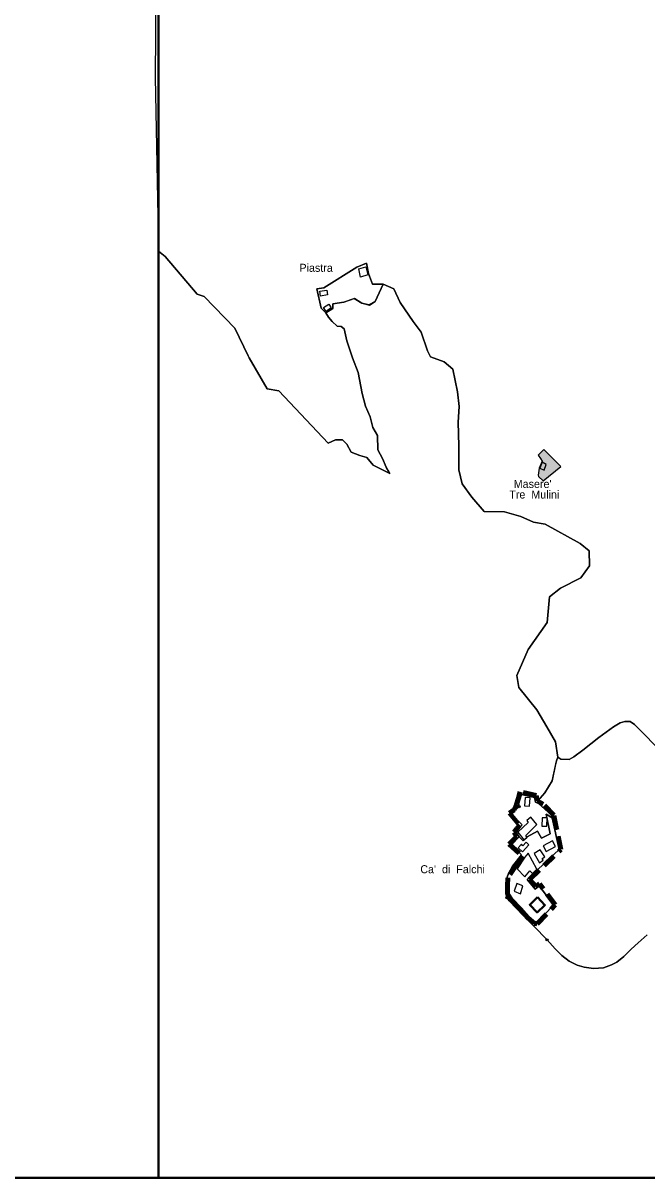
# Model space of a CAD drawing. Extents: x 650071 to 653841, y 889105 to 891996.
# Drawn here: x 652006 to 652784, y 889106 to 890549 of the extents above; entities that cross this region are included whole.
import ezdxf
from ezdxf.enums import TextEntityAlignment as Align

# ---------------------------------------------------------------- set-up
doc = ezdxf.new("R2010")
doc.units = 0
doc.header["$LTSCALE"] = 5.6
doc.header["$PDMODE"] = 32
doc.header["$PDSIZE"] = 2.8
doc.linetypes.add('MEDIUM_DASHED', pattern=[4.5, 3, -1.5])
for name, color, linetype, lineweight in [('2', 7, 'Continuous', 25), ('35', 7, 'Continuous', 25), ('36', 7, 'Continuous', 25), ('4', 7, 'Continuous', 25), ('61', 7, 'Continuous', 35), ('7', 7, 'MEDIUM_DASHED', 100), ('9', 7, 'Continuous', 25)]:
    doc.layers.add(name, color=color, linetype=linetype, lineweight=lineweight)
doc.layers.add('60', color=7, linetype='Continuous')

msp = doc.modelspace()

# ---------------------------------------------------------------- hatches: boundary and pattern name
at = {"layer": '4'}
msp.add_hatch(color=256, dxfattribs=at).paths.add_polyline_path([(652655.57, 890015.75), (652648.32, 890008.92), (652651.05, 890004.87), (652653.25, 890001.32), (652649.63, 889992.42), (652648.51, 889983.98), (652648.82, 889982.17), (652654.45, 889976.86), (652676.76, 889994.67), (652665.71, 890005.72)])

# ---------------------------------------------------------------- linework, layer by layer
at = {"layer": '2'}
msp.add_line((652624.6, 889569.84), (652624.59, 889569.83), dxfattribs=at)
for points in [[(652377.6, 890192.29), (652383.35, 890186.8), (652391.89, 890192.09), (652391.89, 890197.96), (652405.78, 890200.12), (652418.69, 890204.43), (652428.28, 890198.94), (652437.78, 890196.44), (652444.72, 890200.9), (652454.95, 890222.42), (652441.45, 890222.42), (652436.5, 890235.92), (652434.15, 890248.87), (652421.85, 890243.82), (652380.85, 890217.82), (652371.93, 890216.56)], [(652424.52, 890241.64), (652433.17, 890244.24), (652435.94, 890233.94), (652426.63, 890231.2)], [(652375.68, 890213.53), (652384.49, 890215.18), (652385.54, 890209.28), (652376.64, 890207.36)], [(652380.52, 890193.31), (652387.11, 890197.45), (652390, 890192.84), (652383.66, 890188.23)], [(652639.32, 889556.57), (652634.25, 889552.43), (652635.75, 889549.99), (652622.96, 889537.94), (652630.67, 889527.97), (652634.43, 889531.16), (652632.93, 889533.8), (652646.66, 889547.54)], [(652643.42, 889511.43), (652649.91, 889499.78), (652654.64, 889502.76), (652653.38, 889505.22), (652656.58, 889507.1), (652650.75, 889515.95)]]:
    msp.add_lwpolyline(points, close=True, dxfattribs=at)
for points in [[(652665.88, 889555.63), (652664.76, 889559.4), (652648.96, 889573.89), (652644.82, 889575.58), (652643.69, 889581.42), (652627.52, 889584.99), (652623.94, 889574.27), (652624.6, 889569.84)], [(652624.59, 889569.83), (652615, 889560.97), (652628.27, 889547.16), (652620.18, 889537.94), (652624.63, 889532.17), (652629.65, 889527.22), (652634.45, 889531.92)], [(652634.45, 889531.92), (652647.45, 889539.26), (652652.53, 889530.41), (652663.25, 889535.87), (652658.17, 889560.53), (652665.88, 889555.63)]]:
    msp.add_lwpolyline(points, dxfattribs=at)
msp.add_point((652624.6, 889569.84), dxfattribs=at)
at = {"layer": '35'}
msp.add_line((652647.63, 889424.95), (652642.73, 889420.34), dxfattribs=at)
for points in [[(652797.51, 889642.88), (652777.09, 889664.15), (652768.53, 889672.56), (652762.98, 889676.17), (652756.38, 889676.17), (652750.52, 889674.66), (652742.42, 889669.71), (652724.26, 889656.34), (652703.99, 889640.27)], [(652703.99, 889640.27), (652693.04, 889632.01), (652687.03, 889628.56), (652676.83, 889629.01), (652673.09, 889631.71), (652671.14, 889626.92), (652670.16, 889622.28)], [(652670.16, 889622.28), (652665.87, 889601.88), (652656.5, 889586.93), (652647.94, 889576.92), (652648.96, 889573.9), (652664.76, 889559.41), (652665.88, 889555.64), (652674.49, 889516.45), (652634.63, 889478.61), (652644.66, 889466.88), (652649.55, 889470.81), (652667.61, 889447.32), (652647.63, 889424.95), (652642.73, 889420.34), (652659.37, 889403.45)], [(652659.37, 889403.45), (652669.67, 889392.14), (652677.73, 889384), (652686.83, 889376.68), (652697.14, 889371.62), (652705.85, 889369.1), (652717.27, 889367.75), (652729.84, 889368.52), (652739.9, 889372.01), (652746.48, 889375.49), (652755.19, 889382.66), (652764.48, 889391.76), (652772.99, 889399.89), (652784.2, 889409.56)]]:
    msp.add_lwpolyline(points, dxfattribs=at)
msp.add_point((652659.37, 889403.45), dxfattribs=at)
at = {"layer": '36'}
msp.add_line((652287.74, 889106.5), (652863.29, 889106.49), dxfattribs=at)
for points in [[(652172.63, 891018.51), (652174.45, 891018.29), (652170.4, 890480.85), (652174.45, 890263.58), (652182.66, 890257.17), (652182.93, 890256.96), (652222.71, 890210), (652231.38, 890206.94)], [(652287.74, 890130.56), (652286.39, 890132.93), (652269.63, 890167.64), (652231.38, 890206.94), (652222.71, 890210), (652182.93, 890256.96), (652174.45, 890263.58), (652174.44, 889106.04), (652287.74, 889106.5)], [(652287.74, 890130.56), (652309.92, 890091.59), (652324.71, 890089.04), (652386.42, 890023.72), (652395.44, 890028.04), (652404.03, 890028.21), (652409.53, 890022.77), (652414.98, 890012.49), (652425.7, 890008.29), (652434.38, 890005.85), (652442.47, 889996.27), (652450.64, 889992.38), (652463.08, 889985.77), (652458.8, 889993.94), (652454.14, 890004.83), (652448.3, 890015.34), (652447.91, 890033.24), (652442.08, 890043.36), (652438.58, 890056.59), (652432.75, 890070.21), (652428.86, 890085.77), (652423.8, 890112.23), (652416.8, 890130.52), (652409.42, 890151.53), (652406.3, 890166.71), (652402.42, 890169.43), (652397.36, 890170.21), (652391.14, 890175.66), (652386.47, 890181.11), (652383.35, 890186.8), (652377.6, 890192.29), (652371.93, 890216.56), (652380.85, 890217.82), (652421.85, 890243.82), (652434.15, 890248.87), (652436.5, 890235.92), (652441.45, 890222.42), (652454.95, 890222.42), (652468.23, 890216.81), (652476.01, 890199.69), (652492.4, 890175.69), (652502.46, 890162.72), (652510.37, 890139.14), (652513.85, 890131.88), (652530.96, 890125.5), (652541.97, 890116.22), (652547.48, 890087.78), (652549.81, 890069.84), (652548.3, 890050.21), (652549.43, 890020.37), (652549.43, 889990.54), (652553.58, 889973.17), (652565.65, 889956.56), (652580.88, 889938.69)], [(652454.95, 890222.42), (652444.72, 890200.9), (652437.08, 890196.79), (652428.28, 890198.94), (652419.04, 890204.69), (652405.78, 890200.12), (652391.89, 890197.96), (652391.89, 890192.09), (652383.35, 890186.8)], [(652580.88, 889938.69), (652565.65, 889956.56), (652553.58, 889973.17), (652549.43, 889990.54), (652549.43, 890020.37), (652548.3, 890050.21), (652549.81, 890069.84), (652547.48, 890087.78), (652541.97, 890116.22), (652530.96, 890125.5), (652513.85, 890131.88), (652510.37, 890139.14), (652502.46, 890162.72), (652492.4, 890175.69), (652476.01, 890199.69), (652468.23, 890216.81), (652454.95, 890222.42)], [(652231.38, 890206.94), (652269.63, 890167.64), (652286.39, 890132.93), (652287.74, 890130.56)], [(652383.35, 890186.8), (652386.47, 890181.11), (652391.14, 890175.66), (652397.36, 890170.21), (652402.42, 890169.43), (652406.3, 890166.71), (652409.42, 890151.53), (652416.8, 890130.52), (652423.8, 890112.23), (652428.86, 890085.77), (652432.75, 890070.21), (652438.58, 890056.59), (652442.08, 890043.36), (652447.91, 890033.24), (652448.3, 890015.34), (652454.14, 890004.83), (652458.8, 889993.94), (652460.4, 889990.89), (652460.52, 889990.66)], [(652460.52, 889990.66), (652463.08, 889985.77), (652450.64, 889992.38), (652442.47, 889996.27), (652434.38, 890005.85), (652425.7, 890008.29), (652414.98, 890012.49), (652409.53, 890022.77), (652404.03, 890028.21), (652395.44, 890028.04), (652386.42, 890023.72), (652324.71, 890089.04), (652309.92, 890091.59), (652287.74, 890130.56)], [(652673.09, 889631.71), (652669.86, 889650.6), (652659.27, 889669.69), (652646.56, 889690.89), (652624.08, 889718.51), (652621.53, 889733.82), (652635.81, 889765.98), (652659.78, 889799.66), (652662.33, 889831.82), (652676.1, 889842.53), (652701.6, 889855.8), (652712.31, 889870.6), (652711.8, 889889.49), (652700.58, 889898.66), (652656.88, 889922.61), (652642.4, 889925.27), (652626.63, 889932.38), (652606.12, 889937.9), (652580.88, 889938.69)], [(652580.88, 889938.69), (652606.12, 889937.9), (652626.63, 889932.38), (652642.4, 889925.27), (652656.88, 889922.61), (652700.58, 889898.66), (652711.8, 889889.49), (652712.31, 889870.6), (652701.6, 889855.8), (652676.1, 889842.53), (652662.33, 889831.82), (652659.78, 889799.66), (652635.81, 889765.98), (652621.53, 889733.82), (652624.08, 889718.51), (652646.56, 889690.89), (652659.27, 889669.69), (652669.86, 889650.6), (652673.09, 889631.71), (652676.83, 889629.01), (652687.03, 889628.56)], [(652687.03, 889628.56), (652693.04, 889632.01), (652703.99, 889640.27), (652724.26, 889656.34), (652742.42, 889669.71), (652750.52, 889674.66), (652756.38, 889676.17), (652762.98, 889676.17), (652768.53, 889672.56), (652777.09, 889664.15), (652797.51, 889642.88), (652814.61, 889626.6), (652823.01, 889620.44), (652839.37, 889614.13), (652865.64, 889606.92)], [(652643.69, 889581.42), (652644.82, 889575.58), (652648.96, 889573.89), (652647.94, 889576.91), (652656.5, 889586.92), (652665.87, 889601.87), (652671.14, 889626.92), (652673.09, 889631.71)], [(652624.6, 889569.84), (652623.94, 889574.27), (652627.52, 889584.99), (652643.69, 889581.42)], [(652739.9, 889372.01), (652729.84, 889368.52), (652717.27, 889367.75), (652705.85, 889369.1), (652697.14, 889371.62), (652686.83, 889376.68), (652677.73, 889384), (652669.67, 889392.14), (652659.37, 889403.45), (652642.73, 889420.34), (652629.45, 889433.72), (652612.04, 889451.99), (652609.5, 889456.05), (652608.15, 889461.29), (652607.98, 889466.36), (652607.89, 889473.14), (652608.35, 889478.34), (652611.38, 889486.46), (652616.5, 889495.5), (652627.74, 889509.51), (652615.47, 889522.52), (652624.63, 889532.17), (652620.18, 889537.94), (652628.27, 889547.16), (652615, 889560.97), (652624.6, 889569.84)], [(652784.2, 889409.56), (652772.99, 889399.89), (652764.48, 889391.76), (652755.19, 889382.66), (652746.48, 889375.49), (652739.9, 889372.01)]]:
    msp.add_lwpolyline(points, dxfattribs=at)
at = {"layer": '4'}
for points in [[(652655.57, 890015.75), (652648.32, 890008.92), (652651.05, 890004.87), (652653.25, 890001.32), (652649.63, 889992.42), (652648.51, 889983.98), (652648.82, 889982.17), (652654.45, 889976.86), (652676.76, 889994.67), (652665.71, 890005.72)], [(652653.16, 889999.95), (652650.31, 889992.64), (652655.76, 889990.29), (652658.49, 889997.23)]]:
    msp.add_lwpolyline(points, close=True, dxfattribs=at)
at = {"layer": '61', "lineweight": 40}
msp.add_line((652174.44, 889106.04), (650071.44, 889106.05), dxfattribs=at)
msp.add_lwpolyline([(653839.81, 891995.66), (653839.8, 889106.04), (652174.44, 889106.04), (652174.45, 891995.66)], close=True, dxfattribs=at)
at = {"layer": '7'}
for points in [[(652612.47, 889561.56), (652625.34, 889546.6), (652622.21, 889543.12), (652618.38, 889537.9), (652621.86, 889532.68), (652611.98, 889522.91), (652629.17, 889507.97), (652622.21, 889498.92), (652610.39, 889480.82), (652609.99, 889470.7), (652610.15, 889460.64), (652614.79, 889453.52), (652625.77, 889441.91), (652635.43, 889431.06), (652643.2, 889424.33), (652647.01, 889423.54), (652669.51, 889447.07), (652650.17, 889473.24), (652645.51, 889470.04), (652637.62, 889478.92), (652676.47, 889516.32), (652671.27, 889542.11), (652667.77, 889559.13), (652654.56, 889572.7), (652647.25, 889576.87), (652645.86, 889583.83), (652626.04, 889588.36)], [(652626.04, 889588.36), (652623.6, 889580.35), (652621.14, 889572.32), (652618.36, 889566.01), (652612.47, 889561.56)]]:
    msp.add_lwpolyline(points, dxfattribs=at)
at = {"layer": '9'}
for points in [[(652631.28, 889570.76), (652637.45, 889570.26), (652638.3, 889580.69), (652632.13, 889581.19)], [(652653.44, 889555.97), (652652.93, 889545.51), (652659.18, 889545.44), (652659.37, 889556.03)], [(652623.48, 889518.51), (652628.88, 889513.52), (652636.77, 889522.06), (652633.3, 889525.27), (652629.38, 889521.03), (652627.45, 889522.81)], [(652654.45, 889521.05), (652658.31, 889513.81), (652669.99, 889520.03), (652666.14, 889527.27)], [(652631.67, 889506.62), (652622.05, 889491.95), (652631.57, 889482.22), (652638, 889489.71), (652641.35, 889486.46), (652646.75, 889491.7), (652635.94, 889511.67)], [(652621.88, 889473.63), (652618.37, 889464.07), (652626.1, 889461.05), (652629.41, 889470.81)]]:
    msp.add_lwpolyline(points, close=True, dxfattribs=at)
for points in [[(652609.5, 889456.05), (652612.04, 889451.99), (652629.45, 889433.72), (652642.73, 889420.34), (652647.63, 889424.95), (652667.61, 889447.31), (652649.55, 889470.8), (652644.66, 889466.87), (652634.63, 889478.6), (652674.49, 889516.44), (652665.88, 889555.63), (652658.17, 889560.53)], [(652658.17, 889560.53), (652663.25, 889535.87), (652652.53, 889530.41), (652647.45, 889539.26), (652634.45, 889531.92), (652629.65, 889527.22), (652624.63, 889532.17), (652615.47, 889522.52), (652627.74, 889509.51)], [(652627.74, 889509.51), (652616.5, 889495.5), (652611.38, 889486.46), (652608.35, 889478.34), (652607.89, 889473.14), (652607.98, 889466.36), (652608.15, 889461.29), (652609.5, 889456.05)]]:
    msp.add_lwpolyline(points, dxfattribs=at)
at = {"layer": '9', "lineweight": 40}
msp.add_lwpolyline([(652647.59, 889456.57), (652637.82, 889447.34), (652646.94, 889437.68), (652656.71, 889446.91)], close=True, dxfattribs=at)
at = {"layer": '9'}
msp.add_point((652609.5, 889456.05), dxfattribs=at)

# ---------------------------------------------------------------- texts
at = {"layer": '60'}
for s, p in [('Piastra', (652371.23, 890237.9)), ("Masere'", (652641.42, 889967.92)), ('Tre  Mulini', (652643.49, 889954.72)), ("Ca'  di  Falchi", (652541.52, 889486.65))]:
    msp.add_text(s, height=10, dxfattribs=at).set_placement(p, align=Align.CENTER)

doc.saveas('drawing.dxf')
